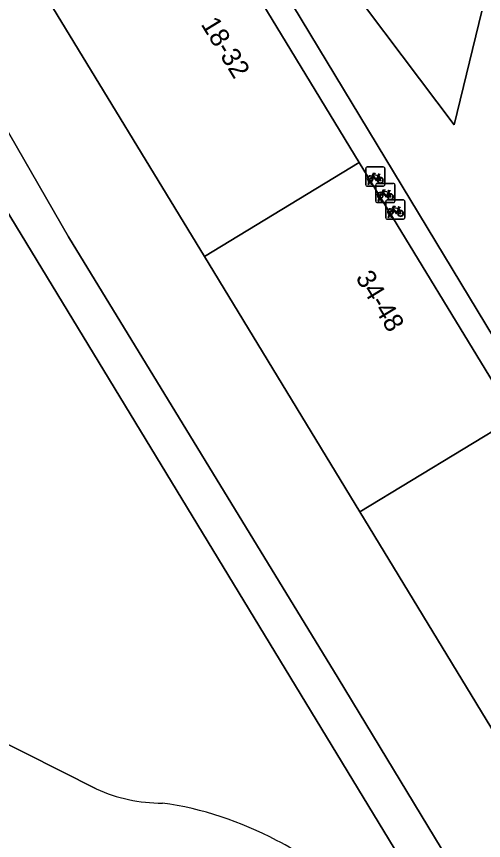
# Model space of a CAD drawing. Extents: x 159888 to 160761, y 384031 to 384750.
# Drawn here: x 160264.55 to 160288.91, y 384622.45 to 384665.45 of the extents above; entities that cross this region are included whole.
import ezdxf

# ---------------------------------------------------------------- set-up
doc = ezdxf.new("R2010")
doc.units = 0
for name, color, linetype in [('IMGEO_Erf', 7, 'Continuous'), ('IMGEO_Fietsenrek', 7, 'Continuous'), ('IMGEO_Groenvoorziening', 7, 'Continuous'), ('IMGEO_Pand', 7, 'Continuous'), ('IMGEO_Pand_nummerreeks', 7, 'Continuous'), ('IMGEO_Parkeervlak_open', 7, 'Continuous'), ('IMGEO_Voetpad_gesloten', 7, 'Continuous'), ('IMGEO_Voetpad_open', 7, 'Continuous')]:
    doc.layers.add(name, color=color, linetype=linetype)

msp = doc.modelspace()

# ---------------------------------------------------------------- linework, layer by layer
at = {"layer": 'IMGEO_Erf'}
for points in [[(160258.508, 384679.247), (160201.065, 384644.22), (160205.593, 384636.587), (160205.248, 384636.301), (160209.474, 384630.138), (160261.252, 384661.738), (160262.987, 384661.364), (160267.258, 384653.953), (160281.338, 384630.928), (160292.129, 384613.093), (160291.528, 384611.183), (160290.976, 384610.866), (160273.725, 384600.111)], [(160285.298, 384600.708), (160298.333, 384608.635), (160300.5, 384609.953), (160298.679, 384612.945), (160290.57, 384626.272), (160282.461, 384639.599), (160274.352, 384652.925), (160266.243, 384666.252)]]:
    msp.add_lwpolyline(points, dxfattribs=at)
at = {"layer": 'IMGEO_Fietsenrek'}
for p, q in [((160282.767, 384656.675), (160282.767, 384657.516)), ((160282.767, 384657.516), (160282.767, 384656.675)), ((160282.842, 384657.6), (160283.683, 384657.6)), ((160283.683, 384657.6), (160282.842, 384657.6)), ((160283.767, 384657.525), (160283.767, 384656.684)), ((160283.767, 384656.684), (160283.767, 384657.525)), ((160282.894, 384656.684), (160282.933, 384656.844)), ((160282.963, 384656.832), (160282.928, 384656.684)), ((160283.005, 384656.856), (160283.004, 384656.86)), ((160283.046, 384656.684), (160283.012, 384656.826)), ((160283.036, 384656.867), (160283.037, 384656.86)), ((160283.044, 384656.83), (160283.079, 384656.684)), ((160283.454, 384657.149), (160283.49, 384657.054)), ((160283.692, 384656.6), (160282.851, 384656.6)), ((160282.851, 384656.6), (160283.692, 384656.6)), ((160282.928, 384656.684), (160282.894, 384656.684)), ((160283.079, 384656.684), (160283.046, 384656.684)), ((160283.292, 384655.814), (160283.292, 384656.655)), ((160283.292, 384656.655), (160283.292, 384655.814)), ((160283.367, 384656.739), (160284.208, 384656.739)), ((160284.208, 384656.739), (160283.367, 384656.739)), ((160284.292, 384656.664), (160284.292, 384655.823)), ((160284.292, 384655.823), (160284.292, 384656.664)), ((160283.419, 384655.823), (160283.458, 384655.983)), ((160283.488, 384655.971), (160283.453, 384655.823)), ((160283.53, 384655.995), (160283.529, 384655.999)), ((160283.571, 384655.823), (160283.537, 384655.965)), ((160283.561, 384656.006), (160283.562, 384655.999)), ((160283.569, 384655.969), (160283.604, 384655.823)), ((160283.979, 384656.288), (160284.015, 384656.193)), ((160284.217, 384655.739), (160283.376, 384655.739)), ((160283.376, 384655.739), (160284.217, 384655.739)), ((160283.453, 384655.823), (160283.419, 384655.823)), ((160283.604, 384655.823), (160283.571, 384655.823)), ((160283.818, 384654.953), (160283.818, 384655.794)), ((160283.818, 384655.794), (160283.818, 384654.953)), ((160283.893, 384655.878), (160284.734, 384655.878)), ((160284.734, 384655.878), (160283.893, 384655.878)), ((160284.818, 384655.803), (160284.818, 384654.962)), ((160284.818, 384654.962), (160284.818, 384655.803)), ((160283.945, 384654.962), (160283.984, 384655.122)), ((160284.014, 384655.11), (160283.979, 384654.962)), ((160284.056, 384655.134), (160284.055, 384655.138)), ((160284.097, 384654.962), (160284.063, 384655.104)), ((160284.087, 384655.145), (160284.088, 384655.138)), ((160284.095, 384655.108), (160284.13, 384654.962)), ((160284.505, 384655.427), (160284.541, 384655.332)), ((160284.743, 384654.878), (160283.902, 384654.878)), ((160283.902, 384654.878), (160284.743, 384654.878)), ((160283.979, 384654.962), (160283.945, 384654.962)), ((160284.13, 384654.962), (160284.097, 384654.962))]:
    msp.add_line(p, q, dxfattribs=at)
for points in [[(160283.08, 384657.126), (160283.175, 384657.29), (160283.261, 384657.276), (160283.263, 384657.267), (160283.207, 384657.256), (160283.18, 384657.211), (160283.436, 384657.17)], [(160283.423, 384657.145), (160283.166, 384657.186), (160283.149, 384657.157), (160283.316, 384656.937), (160283.423, 384657.145)], [(160283.436, 384657.17), (160283.461, 384657.219), (160283.455, 384657.223), (160283.432, 384657.227), (160283.42, 384657.234), (160283.419, 384657.237), (160283.421, 384657.242), (160283.516, 384657.227), (160283.518, 384657.217), (160283.508, 384657.204), (160283.496, 384657.198), (160283.482, 384657.204), (160283.454, 384657.149)], [(160283.101, 384657.074), (160283.049, 384656.984), (160283.009, 384656.959), (160283.01, 384657.006), (160283.065, 384657.1)], [(160283.376, 384656.882), (160283.326, 384656.882), (160283.135, 384657.133), (160283.116, 384657.101)], [(160283.471, 384657.047), (160283.441, 384657.124), (160283.332, 384656.906), (160283.375, 384656.906)], [(160283.405, 384656.906), (160283.525, 384656.905), (160283.481, 384657.019)], [(160283.501, 384657.026), (160283.556, 384656.881), (160283.406, 384656.881)], [(160283.605, 384656.265), (160283.7, 384656.429), (160283.786, 384656.415), (160283.788, 384656.406), (160283.732, 384656.395), (160283.705, 384656.35), (160283.961, 384656.309)], [(160283.948, 384656.284), (160283.691, 384656.325), (160283.674, 384656.296), (160283.841, 384656.076), (160283.948, 384656.284)], [(160283.961, 384656.309), (160283.986, 384656.358), (160283.98, 384656.362), (160283.957, 384656.366), (160283.945, 384656.373), (160283.944, 384656.376), (160283.946, 384656.381), (160284.041, 384656.366), (160284.043, 384656.356), (160284.033, 384656.343), (160284.021, 384656.337), (160284.007, 384656.343), (160283.979, 384656.288)], [(160283.626, 384656.213), (160283.574, 384656.123), (160283.534, 384656.098), (160283.535, 384656.145), (160283.59, 384656.239)], [(160283.901, 384656.021), (160283.851, 384656.021), (160283.66, 384656.272), (160283.641, 384656.24)], [(160283.996, 384656.186), (160283.966, 384656.263), (160283.857, 384656.045), (160283.9, 384656.045)], [(160283.93, 384656.045), (160284.05, 384656.044), (160284.006, 384656.158)], [(160284.026, 384656.165), (160284.081, 384656.02), (160283.931, 384656.02)], [(160284.131, 384655.404), (160284.226, 384655.568), (160284.312, 384655.554), (160284.314, 384655.545), (160284.258, 384655.534), (160284.231, 384655.489), (160284.487, 384655.448)], [(160284.474, 384655.423), (160284.217, 384655.464), (160284.2, 384655.435), (160284.367, 384655.215), (160284.474, 384655.423)], [(160284.487, 384655.448), (160284.512, 384655.497), (160284.506, 384655.501), (160284.483, 384655.505), (160284.471, 384655.512), (160284.47, 384655.515), (160284.472, 384655.52), (160284.567, 384655.505), (160284.569, 384655.495), (160284.559, 384655.482), (160284.547, 384655.476), (160284.533, 384655.482), (160284.505, 384655.427)], [(160284.152, 384655.352), (160284.1, 384655.262), (160284.06, 384655.237), (160284.061, 384655.284), (160284.116, 384655.378)], [(160284.427, 384655.16), (160284.377, 384655.16), (160284.186, 384655.411), (160284.167, 384655.379)], [(160284.522, 384655.325), (160284.492, 384655.402), (160284.383, 384655.184), (160284.426, 384655.184)], [(160284.456, 384655.184), (160284.576, 384655.183), (160284.532, 384655.297)], [(160284.552, 384655.304), (160284.607, 384655.159), (160284.457, 384655.159)]]:
    msp.add_lwpolyline(points, dxfattribs=at)
for centre, radius, start, end in [((160282.845, 384657.522), 0.0779, 92.4484, 184.2845), ((160282.845, 384657.522), 0.0779, 92.4484, 184.2845), ((160283.689, 384657.522), 0.0779, 2.4484, 94.2845), ((160283.689, 384657.522), 0.0779, 2.4484, 94.2845), ((160283.007, 384656.985), 0.159, 62.6766, 242.1369), ((160283.007, 384656.985), 0.129, 63.3192, 238.903), ((160282.987, 384656.856), 0.0499, 12.8025, 158.6934), ((160283.007, 384656.985), 0.159, 253.9967, 271.7867), ((160282.987, 384656.856), 0.0174, 12.8025, 163.4502), ((160283.007, 384656.985), 0.129, 253.415, 269.0204), ((160283.007, 384656.985), 0.129, 283.6043, 43.4302), ((160283.007, 384656.985), 0.159, 283.5766, 46.6042), ((160283.534, 384656.901), 0.159, 113.3408, 178.3217), ((160283.534, 384656.901), 0.159, 187.0065, 105.7708), ((160283.534, 384656.901), 0.129, 113.923, 177.9556), ((160283.534, 384656.901), 0.129, 188.6715, 104.5883), ((160282.845, 384656.678), 0.0779, 182.4484, 274.2845), ((160282.845, 384656.678), 0.0779, 182.4484, 274.2845), ((160283.37, 384656.661), 0.0779, 92.4484, 184.2845), ((160283.37, 384656.661), 0.0779, 92.4484, 184.2845), ((160283.689, 384656.678), 0.0779, 272.4484, 4.2845), ((160283.689, 384656.678), 0.0779, 272.4484, 4.2845), ((160284.214, 384656.661), 0.0779, 2.4484, 94.2845), ((160284.214, 384656.661), 0.0779, 2.4484, 94.2845), ((160283.532, 384656.124), 0.159, 62.6766, 242.1369), ((160283.532, 384656.124), 0.129, 63.3192, 238.903), ((160283.512, 384655.995), 0.0499, 12.8025, 158.6934), ((160283.532, 384656.124), 0.159, 253.9967, 271.7867), ((160283.512, 384655.995), 0.0174, 12.8025, 163.4502), ((160283.532, 384656.124), 0.129, 253.415, 269.0204), ((160283.532, 384656.124), 0.129, 283.6043, 43.4302), ((160283.532, 384656.124), 0.159, 283.5766, 46.6042), ((160284.059, 384656.04), 0.159, 113.3408, 178.3217), ((160284.059, 384656.04), 0.159, 187.0065, 105.7708), ((160284.059, 384656.04), 0.129, 113.923, 177.9556), ((160284.059, 384656.04), 0.129, 188.6715, 104.5883), ((160283.37, 384655.817), 0.0779, 182.4484, 274.2845), ((160283.37, 384655.817), 0.0779, 182.4484, 274.2845), ((160283.896, 384655.8), 0.0779, 92.4484, 184.2845), ((160283.896, 384655.8), 0.0779, 92.4484, 184.2845), ((160284.214, 384655.817), 0.0779, 272.4484, 4.2845), ((160284.214, 384655.817), 0.0779, 272.4484, 4.2845), ((160284.74, 384655.8), 0.0779, 2.4484, 94.2845), ((160284.74, 384655.8), 0.0779, 2.4484, 94.2845), ((160284.058, 384655.263), 0.159, 62.6766, 242.1369), ((160284.058, 384655.263), 0.129, 63.3192, 238.903), ((160284.038, 384655.134), 0.0499, 12.8025, 158.6934), ((160284.058, 384655.263), 0.159, 253.9967, 271.7867), ((160284.038, 384655.134), 0.0174, 12.8025, 163.4502), ((160284.058, 384655.263), 0.129, 253.415, 269.0204), ((160284.058, 384655.263), 0.129, 283.6043, 43.4302), ((160284.058, 384655.263), 0.159, 283.5766, 46.6042), ((160284.585, 384655.179), 0.159, 113.3408, 178.3217), ((160284.585, 384655.179), 0.159, 187.0065, 105.7708), ((160284.585, 384655.179), 0.129, 113.923, 177.9556), ((160284.585, 384655.179), 0.129, 188.6715, 104.5883), ((160283.896, 384654.956), 0.0779, 182.4484, 274.2845), ((160283.896, 384654.956), 0.0779, 182.4484, 274.2845), ((160284.74, 384654.956), 0.0779, 272.4484, 4.2845), ((160284.74, 384654.956), 0.0779, 272.4484, 4.2845)]:
    msp.add_arc(centre, radius, start, end, dxfattribs=at)
at = {"layer": 'IMGEO_Groenvoorziening'}
for points in [[(160288.027, 384615.837), (160263.16, 384656.744)], [(160242.46, 384644.469), (160247.423, 384638.629), (160252.932, 384633.841), (160257.559, 384630.769), (160268.703, 384625.143)]]:
    msp.add_lwpolyline(points, dxfattribs=at)
for centre, radius, start, end in [((160272.155, 384632.871), 8.464, 245.9287, 270.0403), ((160269.734, 384606.994), 17.582, 61.5565, 82.0656), ((160275.436, 384616.548), 6.481, 30.2469, 65.6555)]:
    msp.add_arc(centre, radius, start, end, dxfattribs=at)
at = {"layer": 'IMGEO_Pand'}
for points in [[(160266.243, 384666.252), (160274.352, 384652.925), (160282.432, 384657.841), (160274.323, 384671.167)], [(160290.541, 384644.514), (160282.432, 384657.841), (160274.352, 384652.925), (160282.461, 384639.599)], [(160290.541, 384644.514), (160282.461, 384639.599), (160290.57, 384626.272), (160298.65, 384631.187)]]:
    msp.add_lwpolyline(points, close=True, dxfattribs=at)
at = {"layer": 'IMGEO_Parkeervlak_open'}
msp.add_lwpolyline([(160280.091, 384669.48), (160287.383, 384659.79), (160288.834, 384665.738)], dxfattribs=at)
at = {"layer": 'IMGEO_Voetpad_gesloten'}
for points in [[(160267.258, 384653.953), (160262.987, 384661.364), (160261.252, 384661.738), (160209.474, 384630.138), (160210.792, 384628.216), (160210.908, 384628.024), (160211.36, 384628.301), (160228.319, 384638.692), (160236.839, 384643.913)], [(160263.16, 384656.744), (160288.027, 384615.837)], [(160273.725, 384600.111), (160290.976, 384610.866), (160291.528, 384611.183), (160292.129, 384613.093), (160281.338, 384630.928), (160267.258, 384653.953)], [(160268.703, 384625.143), (160257.559, 384630.769), (160252.932, 384633.841)]]:
    msp.add_lwpolyline(points, dxfattribs=at)
for centre, radius, start, end in [((160272.155, 384632.871), 8.464, 245.9287, 270.0403), ((160269.734, 384606.994), 17.582, 61.5565, 82.0656), ((160275.436, 384616.548), 6.481, 30.2469, 65.6555)]:
    msp.add_arc(centre, radius, start, end, dxfattribs=at)
at = {"layer": 'IMGEO_Voetpad_open'}
for points in [[(160271.929, 384684.273), (160269.481, 384685.954), (160267.612, 384684.826), (160315.278, 384605.986), (160314.349, 384605.388), (160317.864, 384600.824), (160319.7, 384601.934), (160320.072, 384602.167), (160321.951, 384603.293)], [(160288.834, 384665.738), (160287.383, 384659.79), (160280.091, 384669.48)]]:
    msp.add_lwpolyline(points, dxfattribs=at)
msp.add_lwpolyline([(160267.612, 384684.826), (160258.508, 384679.247), (160259.438, 384677.719), (160259.575, 384677.802), (160260.082, 384676.969), (160265.09, 384680.017), (160264.228, 384682.398), (160266.608, 384683.846), (160274.323, 384671.167), (160282.432, 384657.841), (160290.541, 384644.514), (160298.65, 384631.187), (160306.76, 384617.86), (160314.349, 384605.388), (160315.278, 384605.986)], close=True, dxfattribs=at)

# ---------------------------------------------------------------- texts
at = {"layer": 'IMGEO_Pand_nummerreeks'}
for s, rotation, p in [('18-32', 301.4205, (160274.144, 384665.05)), ('34-48', 301.1593, (160282.213, 384651.823))]:
    msp.add_text(s, height=1, rotation=rotation, dxfattribs=at).set_placement(p)

doc.saveas('drawing.dxf')
